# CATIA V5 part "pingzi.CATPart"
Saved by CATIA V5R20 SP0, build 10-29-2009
Part number: 可乐饮料瓶
Material "Bright Plastic": density 1200 kg/m3, Young's modulus 2.2e+09 Pa, Poisson ratio 0.38, thermal expansion 6.84e-05 1/K
Bounding box of the stored display mesh (mm): x 0 to 50, y -50 to 0, z 0 to 110
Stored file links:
  C:\Users\ysz\Desktop\新建文件夹\pingzi.CATPart
  F:\CATIA\Part2.CATPart
  e:\Program Files\Dassault Systemes\B17\intel_a\startup\materials\Simplified_Chinese\Catalog.CATMaterial
  D:\CATIAR20\win_b64\startup\materials\DS_star.jpg
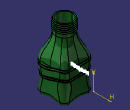
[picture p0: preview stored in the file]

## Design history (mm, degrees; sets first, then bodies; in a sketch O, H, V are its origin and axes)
Set1 "几何图形集.1"
  Point1: type OnCurve, Support edge [face of Pad1 from Sketch11.L1 | face of Pad1 from Sketch11.L2], Ratio 0.5
  Point2: type OnCurve, Support edge [face of Pad1 from Sketch11.L2 | face of Pad1 from Sketch11.L3], Ratio 0.5
  Point3: type OnCurve, Support edge [face of Pad1 from Sketch11.L3 | face of Pad1 from Sketch11.L4], Ratio 0.5
  Point4: type OnCurve, Support edge [face of Pad1 from Sketch11.L4 | face of Pad1 from Sketch11.L1], Ratio 0.5
  Point5: type OnCurve, Support edge [start face of Pad1 | face of Pad1 from Sketch11.L2], Ratio 0.5
  Point6: type OnCurve, Support edge [start face of Pad1 | face of Pad1 from Sketch11.L3], Ratio 0.5
  Point7: type OnCurve, Support edge [start face of Pad1 | face of Pad1 from Sketch11.L4], Ratio 0.5
  Point8: type OnCurve, Support edge [start face of Pad1 | face of Pad1 from Sketch11.L1], Ratio 0.5
  Plane1: type Offset, RefPlane end face of Pad1, Offset 40, reversed
  Point9: type OnCurve, Support edge [face of Pad1 from Sketch11.L1 | end face of Pad1], Ratio 0.5
  Sketch1 "草图.3" on start face of Pad2, origin (0, 0, 90), H (1, 0, 0), V (0, -1, 0)
    point P1 (25, 10)
    reference projected circle E1 centre (25, 25) radius 15 from edge [face of Pad2 from Sketch12.A1 | start face of Pad2]
    distance P1 V = 25
    coincidence: P1 E1
  Boundary1: Boundary {extract ExtractElem end face of Pad1}
  Boundary2: Boundary {extract ExtractElem start face of Pad2}
  Sketch2 "草图.4" on face of Pad1 from Sketch11.L2, origin (50, 0, 0), H (0, 1, 0), V (0, 0, 1)
    spline S1 through (-55, 35) (-30, 30) (-15, 35) (15, 30)
    point P1 (15, 30)
    point P2 (-15, 35)
    point P3 (-30, 30)
    point P4 (-55, 35)
    distance P1 V = 15
    distance P2 V = 15
    distance P1 H = 30
    distance P3 H = 30
    distance P3 V = 30
    distance P2 H = 35
    distance P4 H = 35
    distance P4 V = 55
  Extrude1: Element1 Sketch2, Lim1 50, Lim2 0
  MultiSel1
  Join1: Elements ({intersect ToIntersect1 Extrude1, ToIntersect2 {extract ExtractElem face of Fillet1}}; {intersect ToIntersect1 Extrude1, ToIntersect2 {extract ExtractElem face of Pad1 from Sketch11.L3}}; {intersect ToIntersect1 Extrude1, ToIntersect2 {extract ExtractElem face of Fillet1}}; {intersect ToIntersect1 Extrude1, ToIntersect2 {extract ExtractElem face of Pad1 from Sketch11.L2}}; {intersect ToIntersect1 Extrude1, ToIntersect2 {extract ExtractElem face of Fillet1}}; {intersect ToIntersect1 Extrude1, ToIntersect2 {extract ExtractElem face of Pad1 from Sketch11.L1}}; {intersect ToIntersect1 Extrude1, ToIntersect2 {extract ExtractElem face of Fillet1}}; {intersect ToIntersect1 Extrude1, ToIntersect2 {extract ExtractElem face of Pad1 from Sketch11.L4}})
  Plane2: type Offset, RefPlane yz-plane, Offset 25
  Sketch3 on Plane2, origin (25, 0, 0), H (0, 1, 0), V (0, 0, 1)
    circle A1 centre (1, 36.455) radius 2
    point P1 (1, 36.455)
    reference projected point E1 (0, 36.455) from vertex [face of MultiSel1 | face of MultiSel1]
    reference projected point E2 (0, 36.455) from vertex [face of MultiSel1 | face of MultiSel1]
    radius A1 = 2
    distance P1 E1 H = 1
    distance P1 E2 V = 0
  Translate1: ToTransfor Extrude1, Direction (0, 0, 1), Length 15
  MultiSel2
  Join2: Elements ({intersect ToIntersect1 Translate1, ToIntersect2 {extract ExtractElem face of Loft1}}; {intersect ToIntersect1 Translate1, ToIntersect2 {extract ExtractElem face of Loft1}}; {intersect ToIntersect1 Translate1, ToIntersect2 {extract ExtractElem face of Pad1 from Sketch11.L2}}; {intersect ToIntersect1 Translate1, ToIntersect2 {extract ExtractElem face of Fillet1}}; {intersect ToIntersect1 Translate1, ToIntersect2 {extract ExtractElem face of Pad1 from Sketch11.L3}}; {intersect ToIntersect1 Translate1, ToIntersect2 {extract ExtractElem face of Fillet1}}; {intersect ToIntersect1 Translate1, ToIntersect2 {extract ExtractElem face of Pad1 from Sketch11.L4}}; {intersect ToIntersect1 Translate1, ToIntersect2 {extract ExtractElem face of Loft1}}; {intersect ToIntersect1 Translate1, ToIntersect2 {extract ExtractElem face of Loft1}}; {intersect ToIntersect1 Translate1, ToIntersect2 {extract ExtractElem face of Loft1}})
  Sketch4 on Plane2, origin (25, 0, 0), H (0, 1, 0), V (0, 0, 1)
    circle A1 centre (-51, 47.0591) radius 2
    point P1 (-51, 47.0591)
    reference projected point E1 (-50, 47.0591) from vertex [face of MultiSel2 | face of MultiSel2]
    reference projected point E2 (-50, 47.0591) from vertex [face of MultiSel2 | face of MultiSel2]
    distance P1 E1 H = 1
    radius A1 = 2
    distance E2 P1 V = 0
  Point10: (25, -10, 94)
  Point11: (25, -25, 110)
  Line1: type PtDir, RefPoint Point11, Direction (0, 0, 1), Start 0, End 20
  Helix1: Direction Line1, RefPoint Point10, Pitch 3, Height 15, TaperAngle 0
  Line2: type PtDir, RefPoint Point10, Direction (0, 1, 0), Start 0, End 2
  Point12: type OnCurve, Support Helix1, Length 2
  Connect1: Curve1 Helix1, Point1 Point12, Tension1 1, Curve2 Line2, Point2 vertex of Line2, Tension2 1
  Line3: type PtDir, RefPoint vertex of Helix1, Direction (0, 1, 0), Start 0, End 2
  Point13: type OnCurve, Support Connect1, Length 2
  Connect2: Curve1 Line3, Point1 vertex of Line3, Tension1 1, Curve2 Connect1, Point2 Point13, Tension2 1
  Circle1: type CtrRad, Start 0, End 180, Center vertex of Connect1, Support {plane type OffsetPt, RefPlane zx-plane, RefPoint vertex of Connect1}, Radius 1, FirstDirection (-1, 0, 0)
Set2 "几何图形集.2"
  Sketch5 on xy-plane, origin (0, 0, 0), H (1, 0, 0), V (0, 1, 0)
    line L1 (48, -48) -> (2, -48)
    line L2 (48, -2) -> (48, -48)
    line L3 (2, -48) -> (2, -2)
    point P1 (2, -2)
    line L4 (2, -2) -> (48, -2)
    distance L2 L3 = 46
    distance L4 L1 = 46
    distance P1 H = 2
    distance P1 V = 2
    horizontal: L1 H, L4 H
    vertical: L2 V, L3 V
    perpendicularity: L4 L2
  Point14: type OnCurve, Support edge [face of Pad3 from Sketch5.L3 | face of Pad3 from Sketch5.L4], Ratio 0.5
  Point15: type OnCurve, Support edge [face of Pad3 from Sketch5.L1 | face of Pad3 from Sketch5.L3], Ratio 0.5
  Point16: type OnCurve, Support edge [face of Pad3 from Sketch5.L4 | face of Pad3 from Sketch5.L2], Ratio 0.5
  Point17: type OnCurve, Support edge [face of Pad3 from Sketch5.L2 | face of Pad3 from Sketch5.L1], Ratio 0.5
  Point18: type OnCurve, Support edge [start face of Pad3 | face of Pad3 from Sketch5.L3], Ratio 0.5
  Point19: type OnCurve, Support edge [start face of Pad3 | face of Pad3 from Sketch5.L4], Ratio 0.5
  Point20: type OnCurve, Support edge [start face of Pad3 | face of Pad3 from Sketch5.L2], Ratio 0.5
  Point21: type OnCurve, Support edge [start face of Pad3 | face of Pad3 from Sketch5.L1], Ratio 0.5
  Sketch6 on Plane1, origin (0, 0, 90), H (1, 0, 0), V (0, -1, 0)
    circle A1 centre (25, 25) radius 13
    point P1 (25, 25)
    radius A1 = 13
    distance P1 H = 25
    distance V P1 = 25
  Point22: type OnCurve, Support edge [face of Pad3 from Sketch5.L4 | end face of Pad3], Ratio 0.5
  Sketch7 on start face of Pad4, origin (0, 0, 90), H (1, 0, 0), V (0, -1, 0)
    point P1 (25, 12)
    reference projected circle E1 centre (25, 25) radius 13 from edge [face of Pad4 from Sketch6.A1 | start face of Pad4]
    distance P1 V = 25
    coincidence: P1 E1
  Boundary3: Boundary {extract ExtractElem start face of Pad4}
  Boundary4: Boundary {extract ExtractElem end face of Pad3}
  MultiSel3
  Join3: Elements ({intersect ToIntersect1 Extrude1, ToIntersect2 {extract ExtractElem face of Fillet4}}; {intersect ToIntersect1 Extrude1, ToIntersect2 {extract ExtractElem face of Pad3 from Sketch5.L3}}; {intersect ToIntersect1 Extrude1, ToIntersect2 {extract ExtractElem face of Fillet4}}; {intersect ToIntersect1 Extrude1, ToIntersect2 {extract ExtractElem face of Pad3 from Sketch5.L4}}; {intersect ToIntersect1 Extrude1, ToIntersect2 {extract ExtractElem face of Fillet4}}; {intersect ToIntersect1 Extrude1, ToIntersect2 {extract ExtractElem face of Pad3 from Sketch5.L2}}; {intersect ToIntersect1 Extrude1, ToIntersect2 {extract ExtractElem face of Fillet4}}; {intersect ToIntersect1 Extrude1, ToIntersect2 {extract ExtractElem face of Pad3 from Sketch5.L1}})
  MultiSel4
  Join4: Elements ({intersect ToIntersect1 Translate1, ToIntersect2 {extract ExtractElem face of Pad3 from Sketch5.L2}}; {intersect ToIntersect1 Translate1, ToIntersect2 {extract ExtractElem face of Loft2}}; {intersect ToIntersect1 Translate1, ToIntersect2 {extract ExtractElem face of Loft2}}; {intersect ToIntersect1 Translate1, ToIntersect2 {extract ExtractElem face of Loft2}}; {intersect ToIntersect1 Translate1, ToIntersect2 {extract ExtractElem face of Loft2}}; {intersect ToIntersect1 Translate1, ToIntersect2 {extract ExtractElem face of Pad3 from Sketch5.L3}}; {intersect ToIntersect1 Translate1, ToIntersect2 {extract ExtractElem face of Fillet4}}; {intersect ToIntersect1 Translate1, ToIntersect2 {extract ExtractElem face of Pad3 from Sketch5.L1}}; {intersect ToIntersect1 Translate1, ToIntersect2 {extract ExtractElem face of Fillet4}}; {intersect ToIntersect1 Translate1, ToIntersect2 {extract ExtractElem face of Loft2}})
  Sketch8 on Plane2, origin (25, 0, 0), H (0, 1, 0), V (0, 0, 1)
    circle A1 centre (-1, 36.6906) radius 2
    point P1 (-1, 36.6906)
    reference projected point E1 (-2, 36.6906) from vertex [face of MultiSel3 | face of MultiSel3]
    reference projected point E2 (-2, 36.6906) from vertex [face of MultiSel3 | face of MultiSel3]
    radius A1 = 2
    distance P1 E1 H = 1
    distance P1 E2 V = 0
  Sketch9 on Plane2, origin (25, 0, 0), H (0, 1, 0), V (0, 0, 1)
    circle A1 centre (-49, 46.1561) radius 2
    point P1 (-49, 46.1561)
    reference projected point E1 (-48, 46.1561) from vertex [face of MultiSel4 | face of MultiSel4]
    reference projected point E2 (-48, 46.1561) from vertex [face of MultiSel4 | face of MultiSel4]
    radius A1 = 2
    distance P1 E1 H = 1
    distance P1 E2 V = 0
  Sketch10 on face of Pad1 from Sketch11.L3, origin (0, -50, 0), H (1, 0, 0), V (0, 0, 1)
    polyline C1
    polyline C2
    polyline C3
    polyline C4
    polyline C5
    polyline C6
    polyline C7
    polyline C8
    polyline C9
    polyline C10
    polyline C11
    polyline C12
    polyline C13
    polyline C14
Body1 (main body), material "Bright Plastic"
  Sketch11 on xy-plane, origin (0, 0, 0), H (1, 0, 0), V (0, 1, 0)
    line L1 (0, 0) -> (50, 0)
    line L2 (50, 0) -> (50, -50)
    line L3 (50, -50) -> (0, -50)
    line L4 (0, -50) -> (0, 0)
    length L2 = 50
    length L3 = 50
    horizontal: L1 H, L3 H
    vertical: L2 V, L4 V
  Pad1: profile Sketch11, direction (0, 0, 1), length 50
  Fillet1: on edge [face of Pad1 from Sketch11.L1 | face of Pad1 from Sketch11.L2]; edge [face of Pad1 from Sketch11.L2 | face of Pad1 from Sketch11.L3]; edge [face of Pad1 from Sketch11.L3 | face of Pad1 from Sketch11.L4]; edge [face of Pad1 from Sketch11.L4 | face of Pad1 from Sketch11.L1]
  Fillet2: on edge [start face of Pad1 | face of Fillet1] (x4); edge [start face of Pad1 | face of Pad1 from Sketch11.L2]; edge [start face of Pad1 | face of Pad1 from Sketch11.L3]; edge [start face of Pad1 | face of Pad1 from Sketch11.L4]; edge [start face of Pad1 | face of Pad1 from Sketch11.L1]
  Sketch12 on Plane1, origin (0, 0, 90), H (1, 0, 0), V (0, -1, 0)
    circle A1 centre (25, 25) radius 15
    point P1 (25, 25)
    radius A1 = 15
    distance P1 H = 25
    distance P1 V = 25
  Pad2: profile Sketch12, direction (0, 0, 1), length 20
  Loft1: solid, Sections (Boundary1; Boundary2), StartFace end face of Pad1, EndFace start face of Pad2
  Slot1: profile Sketch3, centre curve Join1
  Slot2: profile Sketch4, centre curve Join2
  Fillet3: radius 1, on edge [face of Fillet1 | face of Slot1] (x3); edge [face of Slot1 | face of Fillet1] (x4); edge [face of Fillet1 | face of Slot2] (x3); edge [face of Loft1 | face of Slot2] (x2); edge [face of Slot2 | face of Fillet1] (x3); edge [face of Slot2 | face of Pad1 from Sketch11.L1]; edge [face of Pad1 from Sketch11.L4 | face of Slot2]; edge [face of Pad1 from Sketch11.L3 | face of Slot2]; edge [face of Slot2 | face of Pad1 from Sketch11.L3]; edge [face of Slot2 | face of Loft1]
  Rib1: profile Circle1, centre curve Connect2
  Body2
    Pad3: profile Sketch5, direction (0, 0, 1), length 50, opposite side length -2
    Fillet4: on edge [face of Pad3 from Sketch5.L4 | face of Pad3 from Sketch5.L2]; edge [face of Pad3 from Sketch5.L2 | face of Pad3 from Sketch5.L1]; edge [face of Pad3 from Sketch5.L3 | face of Pad3 from Sketch5.L4]; edge [face of Pad3 from Sketch5.L1 | face of Pad3 from Sketch5.L3]
    Fillet5: on edge [start face of Pad3 | face of Fillet4] (x4); edge [start face of Pad3 | face of Pad3 from Sketch5.L4]; edge [start face of Pad3 | face of Pad3 from Sketch5.L2]; edge [start face of Pad3 | face of Pad3 from Sketch5.L1]; edge [start face of Pad3 | face of Pad3 from Sketch5.L3]
    Pad4: profile Sketch6, direction (0, 0, 1), length 20
    Loft2: solid, Sections (Boundary3; Boundary4), StartFace start face of Pad4, EndFace end face of Pad3
    Slot3: profile Sketch8, centre curve Join3
    Slot4: profile Sketch9, centre curve Join4
  Remove1: tool Body2
Body3
  Sketch13 on yz-plane, origin (0, 0, 0), H (0, 1, 0), V (0, 0, 1)
    polyline C1
    polyline C2
    polyline C3
    polyline C4
    polyline C5
    polyline C6
    polyline C7
    polyline C8
    polyline C9
    polyline C10
    polyline C11
    polyline C12
    polyline C13
    polyline C14
    polyline C15
    polyline C16
    polyline C17
    polyline C18
    polyline C19
    polyline C20
    polyline C21
    polyline C22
